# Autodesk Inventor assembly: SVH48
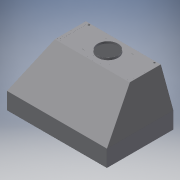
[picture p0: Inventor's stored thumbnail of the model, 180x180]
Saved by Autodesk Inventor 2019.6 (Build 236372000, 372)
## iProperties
Company: none
Created: 2025-04
Part Number: SVH48
Description: CATIA V5 STEP
Document SubType Name: Assembly
Designer: MMAK
Authority: none
Title: C:\Users\MMAK\Documents\SmarTeam\WEBSITE CAD\2025 TRADEWIND HOODS\SVH48.stp
Author: none
Revision Number: ANY
Sending System: CATIA V5 STEP AP203 v2
Preprocessor: CATIA Unofficial Packaging Version SP2
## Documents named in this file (10)
- C:\Users\MMAK\Documents\SmarTeam\WEBSITE CAD\2025 TRADEWIND HOODS\SVH48.iam
- C:\Users\MMAK\Documents\SmarTeam\WEBSITE CAD\2025 TRADEWIND HOODS\P7248-xx-07 face.ipt
- C:\Users\MMAK\Documents\SmarTeam\WEBSITE CAD\2025 TRADEWIND HOODS\P72xx-xx-03 left end.ipt
- C:\Users\MMAK\Documents\SmarTeam\WEBSITE CAD\2025 TRADEWIND HOODS\Blower Mount Plate and Collar.iam
- C:\Users\MMAK\Documents\SmarTeam\WEBSITE CAD\2025 TRADEWIND HOODS\x7248-xx-11 divider.ipt
- C:\Users\MMAK\Documents\SmarTeam\WEBSITE CAD\2025 TRADEWIND HOODS\x7248-xx-32 lightbar.ipt
- C:\Users\MMAK\Documents\SmarTeam\WEBSITE CAD\2025 TRADEWIND HOODS\Blowers Mount Plate Rear.ipt
- C:\Users\MMAK\Documents\SmarTeam\WEBSITE CAD\2025 TRADEWIND HOODS\x7248-xx-05 SS Rear Angle.ipt
- C:\Users\MMAK\Documents\SmarTeam\WEBSITE CAD\2025 TRADEWIND HOODS\P7248-12-01 back.ipt
- C:\Users\MMAK\Documents\SmarTeam\WEBSITE CAD\2025 TRADEWIND HOODS\P72xx-xx-02 right end.ipt
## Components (9 placed, 9 different names)
1. NAUO1
2. NAUO4
3. NAUO9 [sub-assembly]
4. NAUO11
5. NAUO12
6. NAUO10
7. NAUO5
8. NAUO2
9. NAUO3
